// Mitsubishi GX Works2 project: FX3G_COM2_ADPRW 主站   PLC: FX3G

PROGRAM MAIN
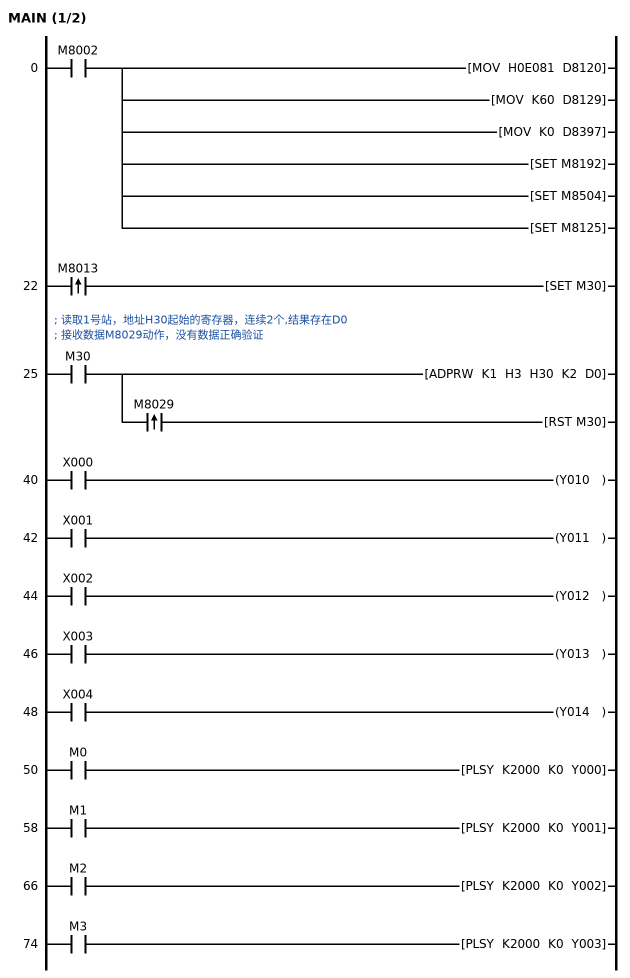
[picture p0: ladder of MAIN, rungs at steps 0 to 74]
0     LD      M8002
      MOV     H0E081 D8120
        [note] 通讯设定9600 8 N 1
      MOV     K60 D8129
        [note] RD3A通讯超时设定
      MOV     K0 D8397
        [note] ADPRW串口2切换
      SET     M8192
        [note] 485模式
      SET     M8504
        [note] RD3A开启
      SET     M8125
        [note] 启用modbus功能
22    LDP     M8013
      SET     M30
; 读取1号站，地址H30起始的寄存器，连续2个,结果存在D0
; 接收数据M8029动作，没有数据正确验证
25    LD      M30
      ADPRW   K1 H3 H30 K2 D0
      ANDP    M8029
      RST     M30
40    LD      X000
      OUT     Y010
42    LD      X001
      OUT     Y011
44    LD      X002
      OUT     Y012
46    LD      X003
      OUT     Y013
48    LD      X004
      OUT     Y014
50    LD      M0
      PLSY    K2000 K0 Y000
58    LD      M1
      PLSY    K2000 K0 Y001
66    LD      M2
      PLSY    K2000 K0 Y002
74    LD      M3
      PLSY    K2000 K0 Y003
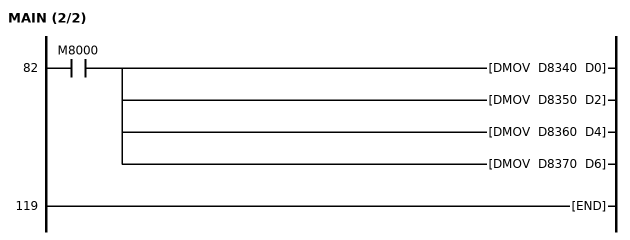
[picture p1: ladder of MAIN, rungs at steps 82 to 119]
82    LD      M8000
      DMOV    D8340 D0
      DMOV    D8350 D2
      DMOV    D8360 D4
      DMOV    D8370 D6
119   END
END_PROGRAM

// device comments not shown above
D200  ; 写入数量，1个
D211  ; 转速
